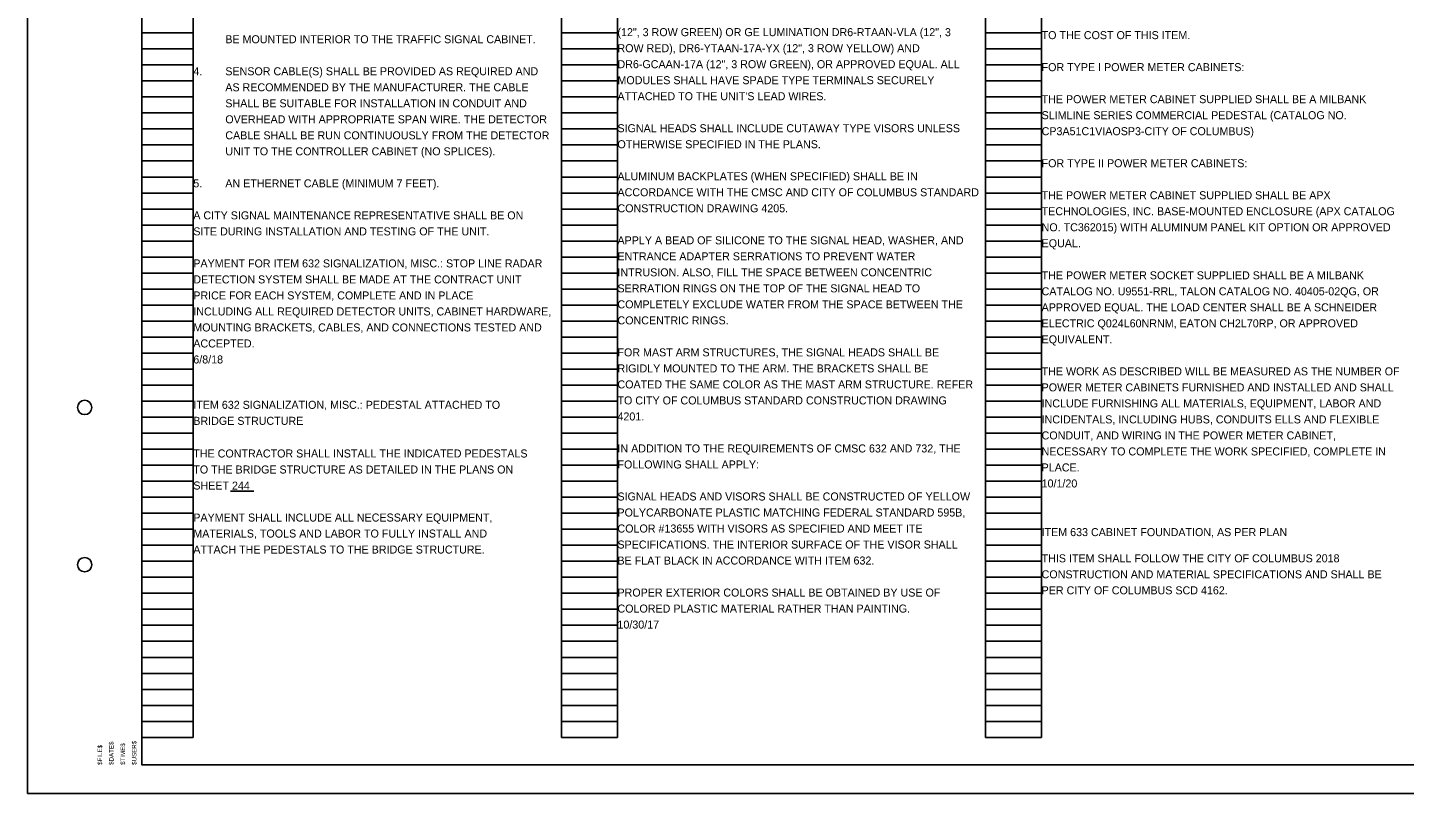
# Model space of a CAD drawing. Extents: x -50.5 to 43.5, y -13 to 19.8.
# Drawn here: x -0.51 to 23.58, y -7.51 to 5.89 of the extents above; entities that cross this region are included whole.
import ezdxf

# ---------------------------------------------------------------- set-up
doc = ezdxf.new("R2010")
doc.units = 0
for name, color, linetype in [('PF_P_Text', 7, 'Continuous'), ('SC_Scratch1', 7, 'Continuous'), ('SH_Cut_Line', 7, 'Continuous'), ('SH_Data', 7, 'Continuous'), ('SH_Text', 7, 'Continuous'), ('SN_P_Text', 7, 'Continuous'), ('TX_P_Misc', 7, 'Continuous')]:
    doc.layers.add(name, color=color, linetype=linetype)

msp = doc.modelspace()

# ---------------------------------------------------------------- linework, layer by layer
at = {"layer": 'PF_P_Text'}
msp.add_lwpolyline([(1.494, 13.992), (32.994, 13.992), (32.994, -7.008), (1.494, -7.008)], close=True, dxfattribs=at)
for centre in [(0.494, -0.758), (0.494, -3.508)]:
    msp.add_circle(centre, 0.125, dxfattribs=at)
at = {"layer": 'SC_Scratch1'}
for p, q in [((1.494, -6.528), (1.494, 13.632)), ((2.394, -6.528), (2.394, 13.632)), ((8.834, -6.528), (8.834, 13.632)), ((9.814, -6.528), (9.814, 13.632)), ((16.254, -6.528), (16.254, 13.632)), ((17.234, -6.528), (17.234, 13.632)), ((1.494, 5.792), (2.394, 5.792)), ((8.834, 5.792), (9.814, 5.792)), ((16.254, 5.792), (17.234, 5.792)), ((1.494, 5.512), (2.394, 5.512)), ((8.834, 5.512), (9.814, 5.512)), ((16.254, 5.512), (17.234, 5.512)), ((1.494, 5.232), (2.394, 5.232)), ((8.834, 5.232), (9.814, 5.232)), ((16.254, 5.232), (17.234, 5.232)), ((1.494, 4.952), (2.394, 4.952)), ((8.834, 4.952), (9.814, 4.952)), ((16.254, 4.952), (17.234, 4.952)), ((1.494, 4.672), (2.394, 4.672)), ((8.834, 4.672), (9.814, 4.672)), ((16.254, 4.672), (17.234, 4.672)), ((1.494, 4.392), (2.394, 4.392)), ((8.834, 4.392), (9.814, 4.392)), ((16.254, 4.392), (17.234, 4.392)), ((1.494, 4.112), (2.394, 4.112)), ((8.834, 4.112), (9.814, 4.112)), ((16.254, 4.112), (17.234, 4.112)), ((1.494, 3.832), (2.394, 3.832)), ((8.834, 3.832), (9.814, 3.832)), ((16.254, 3.832), (17.234, 3.832)), ((1.494, 3.552), (2.394, 3.552)), ((8.834, 3.552), (9.814, 3.552)), ((16.254, 3.552), (17.234, 3.552)), ((1.494, 3.272), (2.394, 3.272)), ((8.834, 3.272), (9.814, 3.272)), ((16.254, 3.272), (17.234, 3.272)), ((1.494, 2.992), (2.394, 2.992)), ((8.834, 2.992), (9.814, 2.992)), ((16.254, 2.992), (17.234, 2.992)), ((1.494, 2.712), (2.394, 2.712)), ((8.834, 2.712), (9.814, 2.712)), ((16.254, 2.712), (17.234, 2.712)), ((1.494, 2.432), (2.394, 2.432)), ((8.834, 2.432), (9.814, 2.432)), ((16.254, 2.432), (17.234, 2.432)), ((1.494, 2.152), (2.394, 2.152)), ((8.834, 2.152), (9.814, 2.152)), ((16.254, 2.152), (17.234, 2.152)), ((1.494, 1.872), (2.394, 1.872)), ((8.834, 1.872), (9.814, 1.872)), ((16.254, 1.872), (17.234, 1.872)), ((1.494, 1.592), (2.394, 1.592)), ((8.834, 1.592), (9.814, 1.592)), ((16.254, 1.592), (17.234, 1.592)), ((1.494, 1.312), (2.394, 1.312)), ((8.834, 1.312), (9.814, 1.312)), ((16.254, 1.312), (17.234, 1.312)), ((1.494, 1.032), (2.394, 1.032)), ((8.834, 1.032), (9.814, 1.032)), ((16.254, 1.032), (17.234, 1.032)), ((1.494, 0.752), (2.394, 0.752)), ((8.834, 0.752), (9.814, 0.752)), ((16.254, 0.752), (17.234, 0.752)), ((1.494, 0.472), (2.394, 0.472)), ((8.834, 0.472), (9.814, 0.472)), ((16.254, 0.472), (17.234, 0.472)), ((1.494, 0.192), (2.394, 0.192)), ((8.834, 0.192), (9.814, 0.192)), ((16.254, 0.192), (17.234, 0.192)), ((1.494, -0.088), (2.394, -0.088)), ((8.834, -0.088), (9.814, -0.088)), ((16.254, -0.088), (17.234, -0.088)), ((1.494, -0.368), (2.394, -0.368)), ((8.834, -0.368), (9.814, -0.368)), ((16.254, -0.368), (17.234, -0.368)), ((1.494, -0.648), (2.394, -0.648)), ((8.834, -0.648), (9.814, -0.648)), ((16.254, -0.648), (17.234, -0.648)), ((1.494, -0.928), (2.394, -0.928)), ((8.834, -0.928), (9.814, -0.928)), ((16.254, -0.928), (17.234, -0.928)), ((1.494, -1.208), (2.394, -1.208)), ((8.834, -1.208), (9.814, -1.208)), ((16.254, -1.208), (17.234, -1.208)), ((1.494, -1.488), (2.394, -1.488)), ((8.834, -1.488), (9.814, -1.488)), ((16.254, -1.488), (17.234, -1.488)), ((1.494, -1.768), (2.394, -1.768)), ((8.834, -1.768), (9.814, -1.768)), ((16.254, -1.768), (17.234, -1.768)), ((1.494, -2.048), (2.394, -2.048)), ((8.834, -2.048), (9.814, -2.048)), ((16.254, -2.048), (17.234, -2.048)), ((1.494, -2.328), (2.394, -2.328)), ((8.834, -2.328), (9.814, -2.328)), ((16.254, -2.328), (17.234, -2.328)), ((1.494, -2.608), (2.394, -2.608)), ((8.834, -2.608), (9.814, -2.608)), ((16.254, -2.608), (17.234, -2.608)), ((1.494, -2.888), (2.394, -2.888)), ((8.834, -2.888), (9.814, -2.888)), ((16.254, -2.888), (17.234, -2.888)), ((1.494, -3.168), (2.394, -3.168)), ((8.834, -3.168), (9.814, -3.168)), ((16.254, -3.168), (17.234, -3.168)), ((1.494, -3.448), (2.394, -3.448)), ((8.834, -3.448), (9.814, -3.448)), ((16.254, -3.448), (17.234, -3.448)), ((1.494, -3.728), (2.394, -3.728)), ((8.834, -3.728), (9.814, -3.728)), ((16.254, -3.728), (17.234, -3.728)), ((1.494, -4.008), (2.394, -4.008)), ((8.834, -4.008), (9.814, -4.008)), ((16.254, -4.008), (17.234, -4.008)), ((1.494, -4.288), (2.394, -4.288)), ((8.834, -4.288), (9.814, -4.288)), ((16.254, -4.288), (17.234, -4.288)), ((1.494, -4.568), (2.394, -4.568)), ((8.834, -4.568), (9.814, -4.568)), ((16.254, -4.568), (17.234, -4.568)), ((1.494, -4.848), (2.394, -4.848)), ((8.834, -4.848), (9.814, -4.848)), ((16.254, -4.848), (17.234, -4.848)), ((1.494, -5.128), (2.394, -5.128)), ((8.834, -5.128), (9.814, -5.128)), ((16.254, -5.128), (17.234, -5.128)), ((1.494, -5.408), (2.394, -5.408)), ((8.834, -5.408), (9.814, -5.408)), ((16.254, -5.408), (17.234, -5.408)), ((1.494, -5.688), (2.394, -5.688)), ((8.834, -5.688), (9.814, -5.688)), ((16.254, -5.688), (17.234, -5.688)), ((1.494, -5.968), (2.394, -5.968)), ((8.834, -5.968), (9.814, -5.968)), ((16.254, -5.968), (17.234, -5.968)), ((1.494, -6.248), (2.394, -6.248)), ((8.834, -6.248), (9.814, -6.248)), ((16.254, -6.248), (17.234, -6.248)), ((1.494, -6.528), (2.394, -6.528)), ((8.834, -6.528), (9.814, -6.528)), ((16.254, -6.528), (17.234, -6.528)), ((-0.506, -7.508), (-0.506, -7.508))]:
    msp.add_line(p, q, dxfattribs=at)
at = {"layer": 'SH_Cut_Line'}
msp.add_lwpolyline([(-0.506, -7.508), (33.494, -7.508), (33.494, 14.492), (-0.506, 14.492)], close=True, dxfattribs=at)
at = {"layer": 'SH_Text'}
msp.add_line((3.453, -2.221), (3.042, -2.221), dxfattribs=at)

# ---------------------------------------------------------------- texts
at = {"layer": 'SH_Data'}
msp.add_text('ITEM 633 CABINET FOUNDATION, AS PER PLAN ', height=0.14, rotation=0, dxfattribs=at).set_placement((17.234, -3.008))
at = {"layer": 'SH_Text'}
for s, p in [('(12", 3 ROW GREEN) OR GE LUMINATION DR6-RTAAN-VLA (12", 3 ', (9.814, 5.735)), ('ROW RED), DR6-YTAAN-17A-YX (12", 3 ROW YELLOW) AND ', (9.814, 5.455)), ('DR6-GCAAN-17A (12", 3 ROW GREEN), OR APPROVED EQUAL. ALL ', (9.814, 5.175)), ('MODULES SHALL HAVE SPADE TYPE TERMINALS SECURELY ', (9.814, 4.895)), ("ATTACHED TO THE UNIT'S LEAD WIRES. ", (9.814, 4.615)), ('SIGNAL HEADS SHALL INCLUDE CUTAWAY TYPE VISORS UNLESS ', (9.814, 4.055)), ('OTHERWISE SPECIFIED IN THE PLANS.', (9.814, 3.775)), ('ALUMINUM BACKPLATES (WHEN SPECIFIED) SHALL BE IN ', (9.814, 3.215)), ('ACCORDANCE WITH THE CMSC AND CITY OF COLUMBUS STANDARD ', (9.814, 2.935)), ('CONSTRUCTION DRAWING 4205.', (9.814, 2.655)), ('APPLY A BEAD OF SILICONE TO THE SIGNAL HEAD, WASHER, AND ', (9.814, 2.095)), ('ENTRANCE ADAPTER SERRATIONS TO PREVENT WATER ', (9.814, 1.815)), ('INTRUSION. ALSO, FILL THE SPACE BETWEEN CONCENTRIC ', (9.814, 1.535)), ('SERRATION RINGS ON THE TOP OF THE SIGNAL HEAD TO ', (9.814, 1.255)), ('COMPLETELY EXCLUDE WATER FROM THE SPACE BETWEEN THE ', (9.814, 0.975)), ('CONCENTRIC RINGS.', (9.814, 0.695)), ('FOR MAST ARM STRUCTURES, THE SIGNAL HEADS SHALL BE ', (9.814, 0.135)), ('RIGIDLY MOUNTED TO THE ARM. THE BRACKETS SHALL BE ', (9.814, -0.145)), ('COATED THE SAME COLOR AS THE MAST ARM STRUCTURE. REFER ', (9.814, -0.425)), ('ITEM 632 SIGNALIZATION, MISC.: PEDESTAL ATTACHED TO ', (2.394, -0.782)), ('TO CITY OF COLUMBUS STANDARD CONSTRUCTION DRAWING ', (9.814, -0.705)), ('BRIDGE STRUCTURE', (2.394, -1.062)), ('4201.', (9.814, -0.985)), ('IN ADDITION TO THE REQUIREMENTS OF CMSC 632 AND 732, THE ', (9.814, -1.545)), ('THE CONTRACTOR SHALL INSTALL THE INDICATED PEDESTALS ', (2.394, -1.633)), ('FOLLOWING SHALL APPLY:', (9.814, -1.825)), ('TO THE BRIDGE STRUCTURE AS DETAILED IN THE PLANS ON ', (2.394, -1.913)), ('SHEET    . ', (2.394, -2.193)), ('244', (3.07, -2.195)), ('SIGNAL HEADS AND VISORS SHALL BE CONSTRUCTED OF YELLOW ', (9.814, -2.385)), ('PAYMENT SHALL INCLUDE ALL NECESSARY EQUIPMENT, ', (2.394, -2.753)), ('POLYCARBONATE PLASTIC MATCHING FEDERAL STANDARD 595B, ', (9.814, -2.665)), ('COLOR #13655 WITH VISORS AS SPECIFIED AND MEET ITE ', (9.814, -2.945)), ('MATERIALS, TOOLS AND LABOR TO FULLY INSTALL AND ', (2.394, -3.033)), ('SPECIFICATIONS. THE INTERIOR SURFACE OF THE VISOR SHALL ', (9.814, -3.225)), ('ATTACH THE PEDESTALS TO THE BRIDGE STRUCTURE.', (2.394, -3.313)), ('BE FLAT BLACK IN ACCORDANCE WITH ITEM 632.', (9.814, -3.505)), ('PROPER EXTERIOR COLORS SHALL BE OBTAINED BY USE OF ', (9.814, -4.065)), ('COLORED PLASTIC MATERIAL RATHER THAN PAINTING.', (9.814, -4.345)), ('10/30/17', (9.814, -4.625))]:
    msp.add_text(s, height=0.14, dxfattribs=at).set_placement(p)
for s, p in [('BE MOUNTED INTERIOR TO THE TRAFFIC SIGNAL CABINET.', (2.954, 5.611)), ('4.', (2.394, 5.051)), ('SENSOR CABLE(S) SHALL BE PROVIDED AS REQUIRED AND ', (2.954, 5.051)), ('AS RECOMMENDED BY THE MANUFACTURER. THE CABLE ', (2.954, 4.771)), ('SHALL BE SUITABLE FOR INSTALLATION IN CONDUIT AND ', (2.954, 4.491)), ('OVERHEAD WITH APPROPRIATE SPAN WIRE. THE DETECTOR ', (2.954, 4.211)), ('CABLE SHALL BE RUN CONTINUOUSLY FROM THE DETECTOR ', (2.954, 3.931)), ('UNIT TO THE CONTROLLER CABINET (NO SPLICES).', (2.954, 3.651)), ('5.', (2.394, 3.091)), ('AN ETHERNET CABLE (MINIMUM 7 FEET).', (2.954, 3.091)), ('A CITY SIGNAL MAINTENANCE REPRESENTATIVE SHALL BE ON ', (2.394, 2.531)), ('SITE DURING INSTALLATION AND TESTING OF THE UNIT.', (2.394, 2.251)), ('PAYMENT FOR ITEM 632 SIGNALIZATION, MISC.: STOP LINE RADAR ', (2.394, 1.691)), ('DETECTION SYSTEM SHALL BE MADE AT THE CONTRACT UNIT ', (2.394, 1.411)), ('PRICE FOR EACH SYSTEM, COMPLETE AND IN PLACE ', (2.394, 1.131)), ('INCLUDING ALL REQUIRED DETECTOR UNITS, CABINET HARDWARE, ', (2.394, 0.851)), ('MOUNTING BRACKETS, CABLES, AND CONNECTIONS TESTED AND ', (2.394, 0.571)), ('ACCEPTED.', (2.394, 0.291)), ('6/8/18', (2.394, 0.011))]:
    msp.add_text(s, height=0.14, rotation=360, dxfattribs=at).set_placement(p)
at = {"layer": 'SN_P_Text'}
for s, p in [('TO THE COST OF THIS ITEM.', (17.234, 5.683)), ('FOR TYPE I POWER METER CABINETS:', (17.234, 5.123)), ('THE POWER METER CABINET SUPPLIED SHALL BE A MILBANK ', (17.234, 4.563)), ('SLIMLINE SERIES COMMERCIAL PEDESTAL (CATALOG NO. ', (17.234, 4.283)), ('CP3A51C1VIAOSP3-CITY OF COLUMBUS)', (17.234, 4.003)), ('FOR TYPE II POWER METER CABINETS:', (17.234, 3.443)), ('THE POWER METER CABINET SUPPLIED SHALL BE APX ', (17.234, 2.883)), ('TECHNOLOGIES, INC. BASE-MOUNTED ENCLOSURE (APX CATALOG ', (17.234, 2.603)), ('NO. TC362015) WITH ALUMINUM PANEL KIT OPTION OR APPROVED ', (17.234, 2.323)), ('EQUAL.', (17.234, 2.043)), ('THE POWER METER SOCKET SUPPLIED SHALL BE A MILBANK ', (17.234, 1.483)), ('CATALOG NO. U9551-RRL, TALON CATALOG NO. 40405-02QG, OR ', (17.234, 1.203)), ('APPROVED EQUAL. THE LOAD CENTER SHALL BE A SCHNEIDER ', (17.234, 0.923)), ('ELECTRIC Q024L60NRNM, EATON CH2L70RP, OR APPROVED ', (17.234, 0.643)), ('EQUIVALENT. ', (17.234, 0.363)), ('THE WORK AS DESCRIBED WILL BE MEASURED AS THE NUMBER OF ', (17.234, -0.197)), ('POWER METER CABINETS FURNISHED AND INSTALLED AND SHALL ', (17.234, -0.477)), ('INCLUDE FURNISHING ALL MATERIALS, EQUIPMENT, LABOR AND ', (17.234, -0.757)), ('INCIDENTALS, INCLUDING HUBS, CONDUITS ELLS AND FLEXIBLE ', (17.234, -1.037)), ('CONDUIT, AND WIRING IN THE POWER METER CABINET, ', (17.234, -1.317)), ('NECESSARY TO COMPLETE THE WORK SPECIFIED, COMPLETE IN ', (17.234, -1.597)), ('PLACE.', (17.234, -1.877)), ('10/1/20', (17.234, -2.157)), ('THIS ITEM SHALL FOLLOW THE CITY OF COLUMBUS 2018 ', (17.234, -3.466)), ('CONSTRUCTION AND MATERIAL SPECIFICATIONS AND SHALL BE ', (17.234, -3.746)), ('PER CITY OF COLUMBUS SCD 4162.', (17.234, -4.026))]:
    msp.add_text(s, height=0.14, rotation=0, dxfattribs=at).set_placement(p)
at = {"layer": 'TX_P_Misc'}
for s, p in [('$FILE$', (0.799, -7.008)), ('$DATE$', (0.999, -7.008)), ('$TIME$', (1.199, -7.008)), ('$USER$', (1.399, -7.008))]:
    msp.add_text(s, height=0.078, rotation=90, dxfattribs=at).set_placement(p)

doc.saveas('drawing.dxf')
